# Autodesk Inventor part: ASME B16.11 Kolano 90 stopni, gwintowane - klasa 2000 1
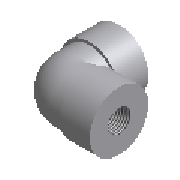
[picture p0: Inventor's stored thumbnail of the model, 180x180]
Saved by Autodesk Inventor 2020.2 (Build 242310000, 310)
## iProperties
Manager: www.cadconsulting.pl
Company: Fabian Stasiak CAD Consulting
NAME: PIPING: ASME B16.11 90 Deg Elbow Threaded - Class 2000
DATA: <meta><inlinegroups number="0" deflen="0"></inlinegroups><connections number="2"></connections><angles><a>1.57079632679489</a></angles></meta>
IsCustomPart: 0
Created: 2014-02
Part Number: ASME B16.11 Kolano 90 stopni, gwintowane - klasa 2000 1
Material: Stal
Description: Kolano 90º, kute, gwintowane - klasa 2000
Document SubType Name: Modeling
Standard: ASME B16.11
Designer: F.Stasiak
Standard Revision: 2005
Standards Organization: ANSI
Language: pl-PL
Size Designation: 1
Categories: <MemberInstance><Categories><Category DisplayName="Rury cienko- i grubościenne" InternalName="4347fa0f-2144-441d-94cd-e3e15c92b736" Mnemonic="TUBEANDPIPE"><Cate
Density: 1 g/cm^3
Appearance: Płyta
Catalog Web Link: www.expertbooks.pl
Author: F.Stasiak
Subject: Zbiór ćwiczeń. Autodesk Inventor 2020. Kurs Professional
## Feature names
1. Sweep1
2. Revolve1
3. Revolve2
4. Revolve3
5. Revolve4
6. Sweep2
## Parameters: MD = 29.69412 mm, A = 38.1 mm, L2 = 17.34312 mm, G = 3.683 mm, d0 = 29.69412 mm, d1 = 45.974 mm, d2 = 0.3124 mm, d3 = 0.3124 mm, d4 = 29.69412 mm, d5 = 45.974 mm, H = 45.974 mm, d6 = 17.34312 mm, d7 = 34.0106 mm, d8 = 17.34312 mm, d9 = 34.0106 mm, d10 = 0, d11 = 7.62 mm, d12 = 7.62 mm, d13 = 20.6883 mm, d14 = 0, d101 = 90 deg, d102 = 90 deg, d105 = 25.4 mm, d106 = 0, d107 = 25.4 mm, d108 = 0, d15 = 38.1 mm, d16 = 20.955 mm, d17 = 38.1 mm, d18 = 20.955 mm, d19 = 41.3766 mm, d20 = 41.3766 mm, d21 = 7.62 mm, d116 = 90 deg, d117 = 90 deg, d22 = 17.00534 mm, d23 = 0, d122 = 0, d123 = 0
